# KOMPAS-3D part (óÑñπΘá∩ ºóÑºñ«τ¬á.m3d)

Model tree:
1. Эскиз:1
2. Операция выдавливания:1
     Расстояние 1 = 6.5
3. Эскиз:2
4. Операция выдавливания:2
     Расстояние 1 = 4; Угол 1 = 63
5. Эскиз:3
6. Операция выдавливания:3
     Расстояние 1 = 2.5
7. Эскиз:4
8. Операция выдавливания:4
     Расстояние 1 = 2.6
9. Эскиз:5
10. Операция выдавливания:5
     Расстояние 1 = 2.6
11. Эскиз:6
12. Вырезать элемент выдавливания:1
     Расстояние 1 = 18.2
13. Массив по концентрической сетке:1  (with: Вырезать элемент выдавливания:1)  (labels: Экземпляр ( 1, 1 ); Экземпляр ( 1, 2 ); Экземпляр ( 1, 3 ); Экземпляр ( 1, 4 ))
     N 2 = 14; Шаг 2 = 360; Номер 2 = 1
14. Эскиз:7
15. Вырезать элемент выдавливания:2
     Расстояние 1 = 0.5
16. Эскиз:8
17. Вырезать элемент выдавливания:3
     Расстояние 1 = 0.5
18. Массив по концентрической сетке:2  (with: Вырезать элемент выдавливания:3)  (labels: Экземпляр ( 1, 1 ); Экземпляр ( 1, 2 ); Экземпляр ( 1, 3 ); Экземпляр ( 1, 4 ))
     N 2 = 14; Шаг 2 = 360; Номер 2 = 1
19. Эскиз:36
20. Вырезать элемент выдавливания:15
     Расстояние 1 = 0.5
21. Эскиз:39
22. Вырезать элемент выдавливания:18
     Расстояние 1 = 1
23. Скругление:18
     Радиус = 0.5
24. Скругление:19
     Радиус = 0.2
25. Скругление:20
     Радиус = 0.5
26. Эскиз:40
27. Вырезать элемент выдавливания:19
     Расстояние 1 = 0.5
28. Эскиз:41
29. Вырезать элемент выдавливания:20
     Расстояние 1 = 0.5
30. Массив по концентрической сетке:11  (with: Вырезать элемент выдавливания:20)  (labels: Экземпляр ( 1, 1 ); Экземпляр ( 1, 2 ); Экземпляр ( 1, 3 ); Экземпляр ( 1, 4 ))
     N 2 = 14; Шаг 2 = 360; Номер 2 = 1
31. Эскиз:42
32. Вырезать элемент выдавливания:21
     Расстояние 1 = 0.5
33. Эскиз:43
34. Вырезать элемент выдавливания:22
     Расстояние 1 = 1
35. Скругление:21
     Радиус = 0.2
36. Эскиз:46
37. Вырезать элемент выдавливания:24
     Расстояние 1 = 14.7
38. Массив по концентрической сетке:13  (with: Вырезать элемент выдавливания:24)  (labels: Экземпляр ( 1, 1 ); Экземпляр ( 1, 2 ); Экземпляр ( 1, 3 ); Экземпляр ( 1, 4 ))
     N 2 = 4; Шаг 2 = 360; Номер 2 = 1
39. Эскиз:47
40. Отверстие:4
41. Эскиз:48
42. Операция выдавливания:20
     Расстояние 1 = 0.7; Расстояние 2 = 15
43. Эскиз:50
44. Операция выдавливания:23
     Расстояние 1 = 0.7; Расстояние 2 = 4.5
45. Эскиз:63
46. Операция выдавливания:28
     Расстояние 1 = 0.7; Расстояние 2 = 5
47. Массив по концентрической сетке:16  (with: Операция выдавливания:23, Операция выдавливания:28)  (labels: Экземпляр ( 1, 1 ); Экземпляр ( 1, 2 ); Экземпляр ( 1, 3 ); Экземпляр ( 1, 4 ))
     N 2 = 4; Шаг 2 = 360; Номер 2 = 1
48. Эскиз:64
49. Отверстие:9
50. Эскиз:65
51. Операция выдавливания:29
     Расстояние 1 = 0.7; Расстояние 2 = 11
52. Скругление:25
     Радиус = 0.1
53. Эскиз:66
54. Вырезать элемент выдавливания:26
     Расстояние 1 = 11
55. Эскиз:67
56. Вырезать элемент выдавливания:27
     Расстояние 1 = 3
57. Скругление:26
     Радиус = 0.1
58. Эскиз:68
59. Вырезать элемент выдавливания:28
     Расстояние 1 = 3
60. Эскиз:69
61. Операция выдавливания:30
     Расстояние 1 = 0.7; Расстояние 2 = 11
62. Эскиз:70
63. Вырезать элемент выдавливания:29
     Расстояние 1 = 0.5
64. Массив по концентрической сетке:17  (with: Операция выдавливания:30, Вырезать элемент выдавливания:29)  (labels: Экземпляр ( 1, 1 ); Экземпляр ( 1, 2 ); Экземпляр ( 1, 3 ); Экземпляр ( 1, 4 ))
     N 2 = 14; Шаг 2 = 360; Номер 2 = 1
65. Смещенная плоскость:3
     Расстояние = 10.3
66. Эскиз:71
67. Операция выдавливания:31
     Расстояние 1 = 0.5; Расстояние 2 = 11
68. Эскиз:72
69. Вырезать элемент выдавливания:30
     Расстояние 1 = 10.8
70. Массив по концентрической сетке:18  (with: Вырезать элемент выдавливания:30)  (labels: Экземпляр ( 1, 1 ); Экземпляр ( 1, 2 ); Экземпляр ( 1, 3 ); Экземпляр ( 1, 4 ))
     N 2 = 4; Шаг 2 = 360; Номер 2 = 1
71. Эскиз:73
72. Операция выдавливания:32
     Расстояние 1 = 10; Расстояние 2 = 5.7
73. Скругление:27
     Радиус = 1
74. Эскиз:74
75. Вырезать элемент выдавливания:31
     Расстояние 1 = 4.7

Referenced files in C:\Program Files\ASCON\KOMPAS-3D V13 Home\Sys\: holelib.lfr
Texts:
  stalker61
  Сплав АЛ8  ГОСТ 1583-93
  Отверстие 02
  (вариант 2)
